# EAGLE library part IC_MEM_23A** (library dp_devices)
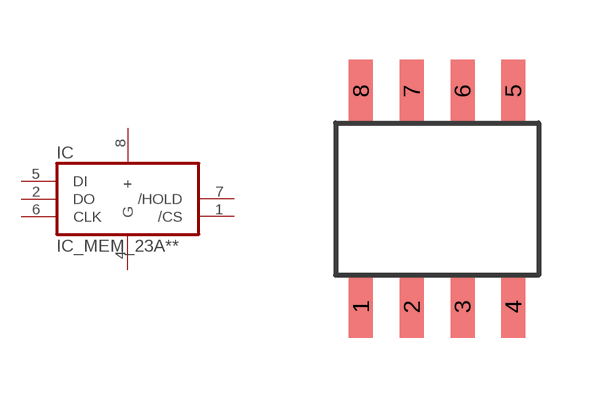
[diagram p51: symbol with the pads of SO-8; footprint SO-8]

Designator prefix IC

## IC_MEM_23ASO8  [SO-8]
1  /CS
2  DO
4  G  pwr
5  DI
6  CLK
7  /HOLD
8  +  pwr

## Footprint SO-8 (pad centres in mm)
smd 0.6 x 1.55: 1 -1.905,-2.69; 2 -0.635,-2.69; 3 0.635,-2.69; 4 1.905,-2.69; 5 1.905,2.71; 6 0.635,2.71; 7 -0.635,2.71; 8 -1.905,2.71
